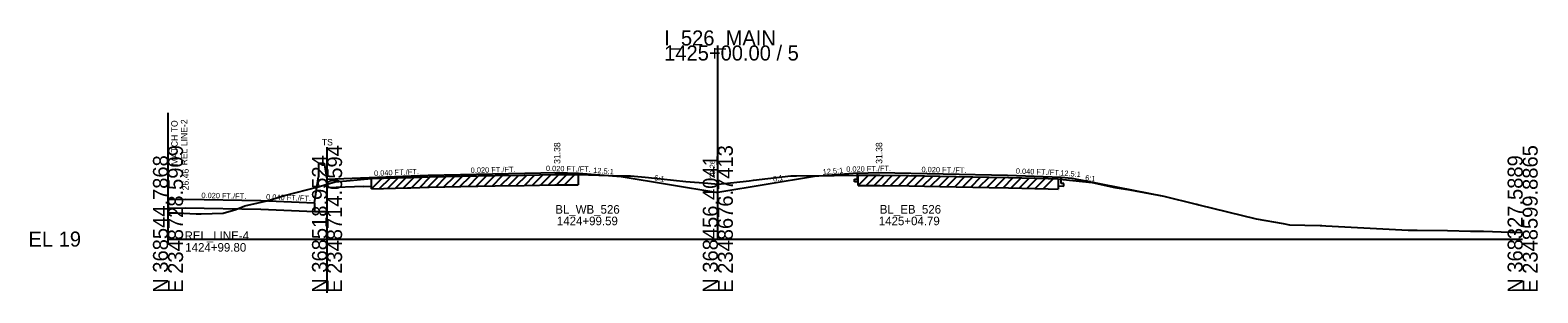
# Model space of a CAD drawing. Extents: x -170 to 2527928, y -10 to 1619750.
# Drawn here: x 3974.3 to 4255.3, y 3990 to 4038.9 of the extents above; entities that cross this region are included whole.
import ezdxf

# ---------------------------------------------------------------- set-up
doc = ezdxf.new("R2010")
doc.units = 0
for name, color, linetype in [('RD_GPK_XS_Cell', 7, 'Continuous'), ('RD_PD_NOISE-WALL-GM', 7, 'Continuous'), ('RD_XS_Base', 7, 'Continuous'), ('RD_XS_EarthShd', 7, 'Continuous'), ('RD_XS_ExGround', 7, 'Continuous'), ('RD_XS_ExPaveRet', 7, 'Continuous'), ('RD_XS_MatchLine', 7, 'Continuous'), ('RD_XS_Pave', 7, 'Continuous'), ('RD_XS_PaveShd', 7, 'Continuous'), ('RD_XS_TieSlope', 7, 'Continuous'), ('RD_XS_TX_Elev_EX', 7, 'Continuous'), ('RD_XS_TX_Slope', 7, 'Continuous'), ('RD_XS_TX_Station', 7, 'Continuous')]:
    doc.layers.add(name, color=color, linetype=linetype)

msp = doc.modelspace()

# ---------------------------------------------------------------- linework, layer by layer
at = {"layer": 'RD_GPK_XS_Cell'}
for p, q in [((4102.48, 4000), (4102.48, 4036.04)), ((4000, 4000), (4029.64, 4000)), ((4029.64, 4000), (4102.48, 4000)), ((4102.48, 4000), (4252.48, 4000))]:
    msp.add_line(p, q, dxfattribs=at)
at = {"layer": 'RD_PD_NOISE-WALL-GM'}
for p, q in [((4028.08, 4014.14), (4029.12, 4014.14)), ((4028.08, 4014.14), (4028.08, 4011.59)), ((4029.12, 4014.14), (4029.6, 4011.14)), ((4027.31, 4006.77), (4028.08, 4011.59)), ((4029.6, 4011.14), (4029.6, 3990)), ((4027.31, 4006.77), (4027.31, 4005.14)), ((4027.31, 4005.14), (4029.64, 4005.14))]:
    msp.add_line(p, q, dxfattribs=at)
at = {"layer": 'RD_XS_Base'}
for p, q in [((4076.48, 4012.01), (4076.48, 4012.3)), ((4127.98, 4011.16), (4128.48, 4011.17)), ((4127.98, 4010.66), (4127.98, 4011.16)), ((4128.48, 4010.67), (4127.98, 4010.66)), ((4128.48, 4011.17), (4128.48, 4012.3)), ((4128.48, 4010.67), (4128.64, 4010.67)), ((4166.48, 4010.37), (4166.48, 4011.5)), ((4166.98, 4010.35), (4166.48, 4010.37)), ((4166.98, 4009.85), (4166.98, 4010.35)), ((4036.48, 4009.78), (4029.6, 4009.51)), ((4036.48, 4009.78), (4037.92, 4009.84)), ((4165.89, 4009.89), (4166.98, 4009.85)), ((4000, 4005.75), (4003.22, 4005.82)), ((4003.22, 4005.82), (4017.31, 4005.54)), ((4017.31, 4005.54), (4027.31, 4005.14))]:
    msp.add_line(p, q, dxfattribs=at)
at = {"layer": 'RD_XS_EarthShd'}
for p, q in [((4076.48, 4012.3), (4084.48, 4011.66)), ((4128.48, 4012.3), (4120.48, 4011.66))]:
    msp.add_line(p, q, dxfattribs=at)
at = {"layer": 'RD_XS_ExGround'}
msp.add_lwpolyline([(4000, 4004.89), (4001.69, 4004.87), (4005.23, 4004.72), (4006.18, 4004.68), (4010.27, 4004.83), (4012.65, 4005.53), (4014.34, 4006.17), (4016.8, 4006.73), (4018.48, 4007.12), (4021.74, 4008.09), (4027.97, 4009.74), (4029.64, 4010.22), (4031.15, 4010.65), (4033.97, 4010.91), (4036.57, 4011.17), (4037.92, 4011.26), (4044.64, 4011.47), (4044.95, 4011.48), (4045.28, 4011.49), (4048.69, 4011.58), (4054.57, 4011.69), (4060.99, 4011.81), (4066.4, 4011.91), (4072.12, 4012.01), (4073.53, 4012), (4076.46, 4012.01), (4084.1, 4011.75), (4086.21, 4011.75), (4088.91, 4011.5), (4091.9, 4011.19), (4096.5, 4010.75), (4100.64, 4010.41), (4102.57, 4010.25), (4107.73, 4010.77), (4108.32, 4010.84), (4109.11, 4010.94), (4116.1, 4011.76), (4117.14, 4011.77), (4124.16, 4011.85), (4128.64, 4011.88), (4130.75, 4011.89), (4132.69, 4011.91), (4138.15, 4011.82), (4143.84, 4011.72), (4153.05, 4011.54), (4156.65, 4011.47), (4164.05, 4011.26), (4165.89, 4011.2), (4166.82, 4011.11), (4172.24, 4010.51), (4176.49, 4009.61), (4179.29, 4009.14), (4185.59, 4007.96), (4191.61, 4006.53), (4191.69, 4006.51), (4191.76, 4006.49), (4192.14, 4006.4), (4202.83, 4003.79), (4207.84, 4002.89), (4209, 4002.64), (4214.75, 4002.52), (4215.08, 4002.5), (4215.78, 4002.44), (4231.12, 4001.69), (4232.84, 4001.64), (4238.5, 4001.61), (4242.79, 4001.5), (4245.17, 4001.45), (4250.13, 4001.31), (4251.45, 4001.26), (4252.48, 4001.24)], dxfattribs=at)
at = {"layer": 'RD_XS_ExPaveRet'}
for p, q in [((4037.92, 4009.34), (4039.9, 4011.32)), ((4037.92, 4009.34), (4037.92, 4011.26)), ((4039.42, 4009.39), (4041.4, 4011.37)), ((4040.92, 4009.44), (4042.9, 4011.42)), ((4042.42, 4009.48), (4044.4, 4011.46)), ((4043.92, 4009.53), (4045.89, 4011.51)), ((4045.42, 4009.58), (4047.39, 4011.54)), ((4046.92, 4009.62), (4048.89, 4011.58)), ((4048.42, 4009.65), (4050.37, 4011.61)), ((4049.92, 4009.68), (4051.87, 4011.64)), ((4051.42, 4009.71), (4053.37, 4011.66)), ((4052.92, 4009.74), (4054.87, 4011.69)), ((4054.42, 4009.77), (4056.37, 4011.72)), ((4055.92, 4009.79), (4057.87, 4011.75)), ((4057.42, 4009.82), (4059.37, 4011.78)), ((4058.92, 4009.85), (4060.87, 4011.8)), ((4060.42, 4009.88), (4062.37, 4011.83)), ((4061.92, 4009.91), (4063.87, 4011.86)), ((4063.42, 4009.93), (4065.37, 4011.89)), ((4064.92, 4009.96), (4066.87, 4011.92)), ((4066.4, 4009.99), (4072.12, 4010.09)), ((4066.42, 4009.99), (4068.37, 4011.94)), ((4067.92, 4010.02), (4069.87, 4011.97)), ((4069.42, 4010.04), (4071.37, 4011.99)), ((4070.92, 4010.07), (4072.86, 4012)), ((4072.12, 4010.09), (4073.53, 4010.08)), ((4072.42, 4010.09), (4074.34, 4012.01)), ((4073.53, 4010.08), (4076.46, 4010.1)), ((4073.92, 4010.09), (4075.85, 4012.01)), ((4076.46, 4012.01), (4076.46, 4010.1)), ((4128.64, 4009.96), (4130.58, 4011.89)), ((4128.64, 4009.96), (4128.64, 4011.88)), ((4130.14, 4009.97), (4132.08, 4011.9)), ((4131.64, 4009.98), (4133.55, 4011.89)), ((4133.14, 4009.98), (4135.03, 4011.87)), ((4134.64, 4009.96), (4136.53, 4011.84)), ((4136.14, 4009.93), (4138.03, 4011.82)), ((4137.64, 4009.91), (4139.53, 4011.79)), ((4139.14, 4009.88), (4141.03, 4011.77)), ((4140.64, 4009.86), (4142.53, 4011.74)), ((4142.14, 4009.83), (4144.03, 4011.71)), ((4143.64, 4009.8), (4145.53, 4011.68)), ((4145.14, 4009.78), (4147.02, 4011.66)), ((4146.64, 4009.75), (4148.52, 4011.63)), ((4148.14, 4009.72), (4150.02, 4011.6)), ((4149.64, 4009.69), (4151.52, 4011.57)), ((4151.14, 4009.66), (4153.02, 4011.54)), ((4152.64, 4009.63), (4154.52, 4011.51)), ((4154.14, 4009.6), (4156.02, 4011.48)), ((4155.64, 4009.57), (4157.52, 4011.45)), ((4157.14, 4009.54), (4159.01, 4011.4)), ((4158.64, 4009.5), (4160.51, 4011.36)), ((4160.14, 4009.45), (4162.01, 4011.32)), ((4161.64, 4009.41), (4163.51, 4011.27)), ((4163.14, 4009.36), (4165.01, 4011.23)), ((4165.89, 4011.2), (4165.89, 4009.29)), ((4037.92, 4009.34), (4044.64, 4009.55)), ((4044.64, 4009.55), (4044.95, 4009.56)), ((4044.95, 4009.56), (4045.28, 4009.57)), ((4045.28, 4009.57), (4048.69, 4009.66)), ((4048.69, 4009.66), (4054.57, 4009.77)), ((4054.57, 4009.77), (4060.99, 4009.89)), ((4060.99, 4009.89), (4066.4, 4009.99)), ((4128.64, 4009.96), (4130.75, 4009.98)), ((4130.75, 4009.98), (4132.69, 4009.99)), ((4132.69, 4009.99), (4138.15, 4009.9)), ((4138.15, 4009.9), (4143.84, 4009.8)), ((4143.84, 4009.8), (4153.05, 4009.62)), ((4153.05, 4009.62), (4156.65, 4009.55)), ((4156.65, 4009.55), (4164.05, 4009.34)), ((4164.05, 4009.34), (4165.89, 4009.29))]:
    msp.add_line(p, q, dxfattribs=at)
at = {"layer": 'RD_XS_MatchLine'}
for p, q in [((4000, 3999.09), (4000, 4023.5)), ((4029.64, 4000), (4029.64, 4017.1))]:
    msp.add_line(p, q, dxfattribs=at)
at = {"layer": 'RD_XS_Pave'}
for p, q in [((4048.48, 4011.9), (4072.48, 4012.38)), ((4132.48, 4012.38), (4156.48, 4011.9)), ((4003.22, 4007.46), (4017.31, 4007.17))]:
    msp.add_line(p, q, dxfattribs=at)
at = {"layer": 'RD_XS_PaveShd'}
for p, q in [((4029.6, 4011.14), (4048.48, 4011.9)), ((4072.48, 4012.38), (4076.48, 4012.3)), ((4128.48, 4012.3), (4132.48, 4012.38)), ((4156.48, 4011.9), (4166.48, 4011.5)), ((4000, 4007.39), (4003.22, 4007.46)), ((4000, 4007.39), (4000, 4004.89)), ((4017.31, 4007.17), (4027.31, 4006.77))]:
    msp.add_line(p, q, dxfattribs=at)
at = {"layer": 'RD_XS_TieSlope'}
for p, q in [((4084.48, 4011.66), (4102.48, 4008.66)), ((4120.48, 4011.66), (4102.48, 4008.66)), ((4166.48, 4011.5), (4168.48, 4011.34)), ((4168.48, 4011.34), (4185.59, 4007.96))]:
    msp.add_line(p, q, dxfattribs=at)

# ---------------------------------------------------------------- texts
at = {"layer": 'RD_GPK_XS_Cell'}
for s, p in [('I_526_MAIN', (4092.48, 4036.04)), ('1425+00.00 / 5', (4092.48, 4033.24)), ('EL 19', (3974, 3998.6))]:
    msp.add_text(s, height=2.8, dxfattribs=at).set_placement(p)
for s, p in [('E 2348728.5909', (4002.8, 3990)), ('E 2348714.0594', (4032.44, 3990)), ('E 2348676.7413', (4105.28, 3990)), ('E 2348599.8865', (4255.28, 3990)), ('N 368544.7868', (4000, 3990)), ('N 368518.9524', (4029.64, 3990)), ('N 368456.4041', (4102.48, 3990)), ('N 368327.5889', (4252.48, 3990))]:
    msp.add_text(s, height=2.8, rotation=90, dxfattribs=at).set_placement(p)
at = {"layer": 'RD_XS_MatchLine'}
msp.add_text('TS', height=1.2, dxfattribs=at).set_placement((4028.67, 4017.43))
at = {"layer": 'RD_XS_TX_Elev_EX'}
msp.add_text('29.26', height=1, rotation=90, dxfattribs=at).set_placement((4101.98, 4011.26))
at = {"layer": 'RD_XS_TX_Slope'}
for s, rotation, p in [('0.040 FT./FT.', 2.2906, (4038.42, 4011.75)), ('0.020 FT./FT.', 1.1458, (4056.42, 4012.31)), ('0.020 FT./FT.', 358.8542, (4070.43, 4012.67)), ('12.5:1', 355.4261, (4079.23, 4012.34)), ('12.5:1', 4.5739, (4122.06, 4012)), ('0.020 FT./FT.', 1.1458, (4126.42, 4012.51)), ('0.020 FT./FT.', 358.8542, (4140.43, 4012.47)), ('0.040 FT./FT.', 357.7094, (4158.01, 4012.18)), ('12.5:1', 355.4261, (4166.27, 4011.84)), ('6:1', 350.5377, (4090.55, 4010.97)), ('6:1', 9.4623, (4112.81, 4010.67)), ('6:1', 352.6182, (4170.89, 4010.96)), ('0.020 FT./FT.', 358.8542, (4006.22, 4007.65)), ('0.040 FT./FT.', 357.7094, (4018.27, 4007.39))]:
    msp.add_text(s, height=1, rotation=rotation, dxfattribs=at).set_placement(p)
at = {"layer": 'RD_XS_TX_Station'}
for s, p in [('MATCH TO', (4001.8, 4013.73)), ('REL LINE-2', (4003.6, 4013.73)), (' 31.38', (4073.13, 4013.55)), (' 31.38', (4133.13, 4013.56)), (' 26.46', (4003.87, 4008.63))]:
    msp.add_text(s, height=1.2, rotation=90, dxfattribs=at).set_placement(p)
for s, p in [('BL_WB_526', (4072.18, 4004.73)), ('BL_EB_526', (4132.67, 4004.74)), ('1424+99.59', (4072.48, 4002.58)), ('1425+04.79', (4132.48, 4002.58)), ('REL_LINE-4', (4003.09, 3999.83)), ('1424+99.80', (4003.22, 3997.66))]:
    msp.add_text(s, height=1.6, dxfattribs=at).set_placement(p)

doc.saveas('drawing.dxf')
